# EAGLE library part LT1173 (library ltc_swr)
LT1173 - Micropower DC/DC Converter Adjustable and Fixed 5V, 12V Operates at Supply Voltages From 2.0V to 30V Consumes Only 110&#181;A Supply Current Works in Step-Up or Step-Down Mode Only Three External Components Required Low Battery Detector Comparator On-Chip User-Adjustable Current Limit Internal 1A Power Switch Fixed or Adjustable Output Voltage Versions Space Saving 8-Pin MiniDIP or SO8 Package
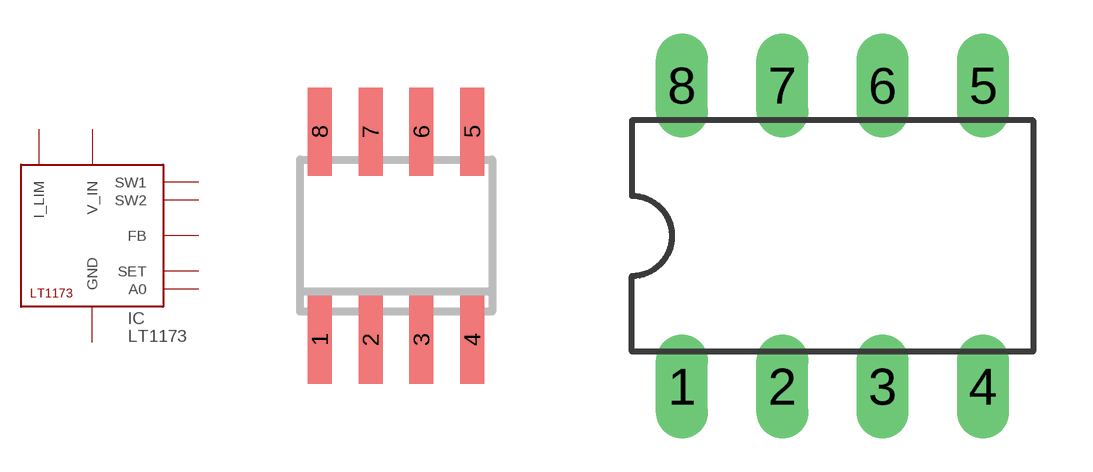
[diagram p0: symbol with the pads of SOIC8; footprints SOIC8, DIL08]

Designator prefix IC

## LT1173CS8  [SOIC8]
1  I_LIM  pas
2  V_IN  pas
3  SW1  pas
4  SW2  pas
5  GND  pwr
6  A0  pas
7  SET  pas
8  FB  pas

## LT1173CN8  [DIL08]
Pads as for SOIC8

## Footprint SOIC8 (pad centres in mm)
Small Outline IC
smd 0.6 x 2.2: 1 -1.905,-2.6; 2 -0.635,-2.6; 3 0.635,-2.6; 4 1.905,-2.6; 5 1.905,2.6; 6 0.635,2.6; 7 -0.635,2.6; 8 -1.905,2.6

## Footprint DIL08 (pad centres in mm)
Dual In Line Package
drill 0.813 long: 1 -3.81,-3.81; 2 -1.27,-3.81; 3 1.27,-3.81; 4 3.81,-3.81; 5 3.81,3.81; 6 1.27,3.81; 7 -1.27,3.81; 8 -3.81,3.81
